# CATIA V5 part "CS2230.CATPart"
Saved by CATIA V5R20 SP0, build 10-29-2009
Part number: CS2230
Revision: 5
Definition: design
Nomenclature: CS2230
Source: made
Description: NOT SPECIFIED
Bounding box of the stored display mesh (mm): x -29 to 29, y -29 to 29, z -55 to 15
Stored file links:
  C:\Users\Raffaele\Desktop\3D X SITO CF\BOLEX\20-TILTED COLUMN SUPPORT\CS2230.CATPart
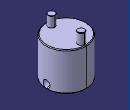
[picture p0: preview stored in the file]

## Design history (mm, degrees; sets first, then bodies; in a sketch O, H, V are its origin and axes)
Body1 "MANIFOLD_SOLID_BREP #740" (main body)
  Solid1: solid without history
